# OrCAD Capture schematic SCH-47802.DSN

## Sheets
1 Title, ToC and Rev History: title: X-KIT-TPLSNIFEVB; rev: A; note: SCH-47802 - SPF-47802
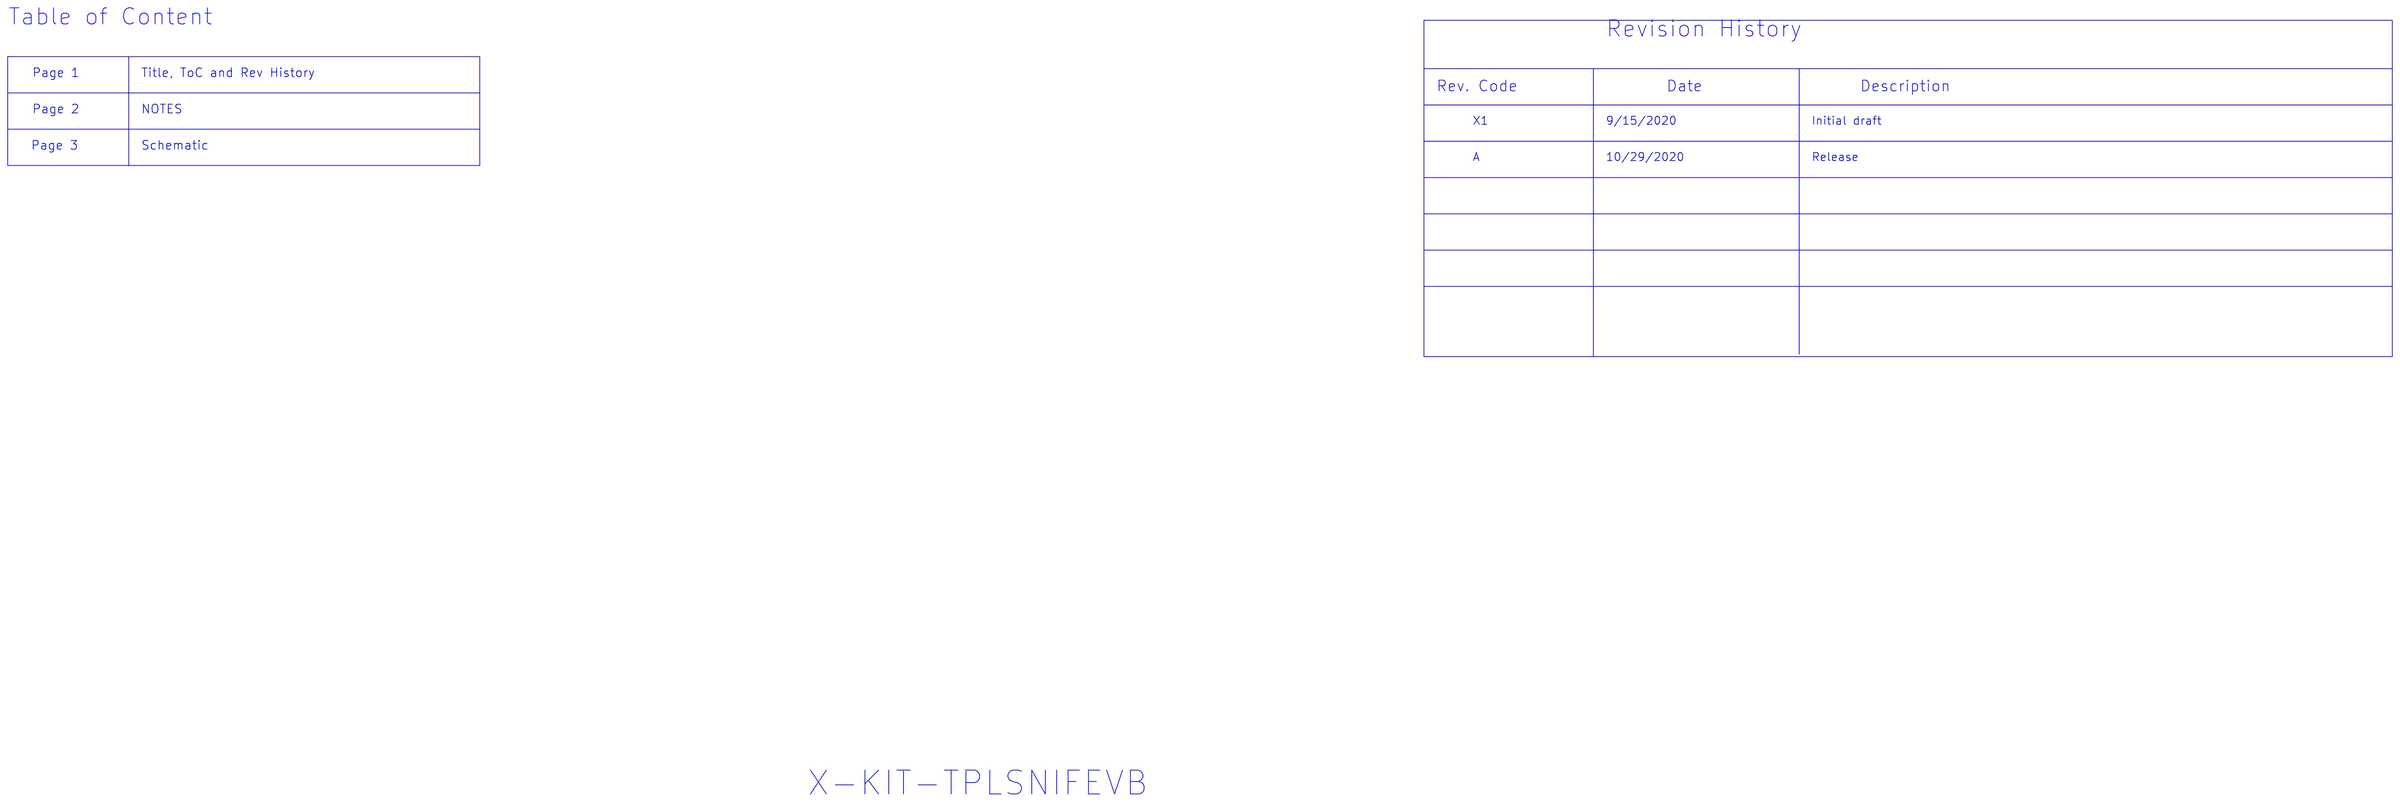
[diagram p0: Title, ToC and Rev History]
2 Notes
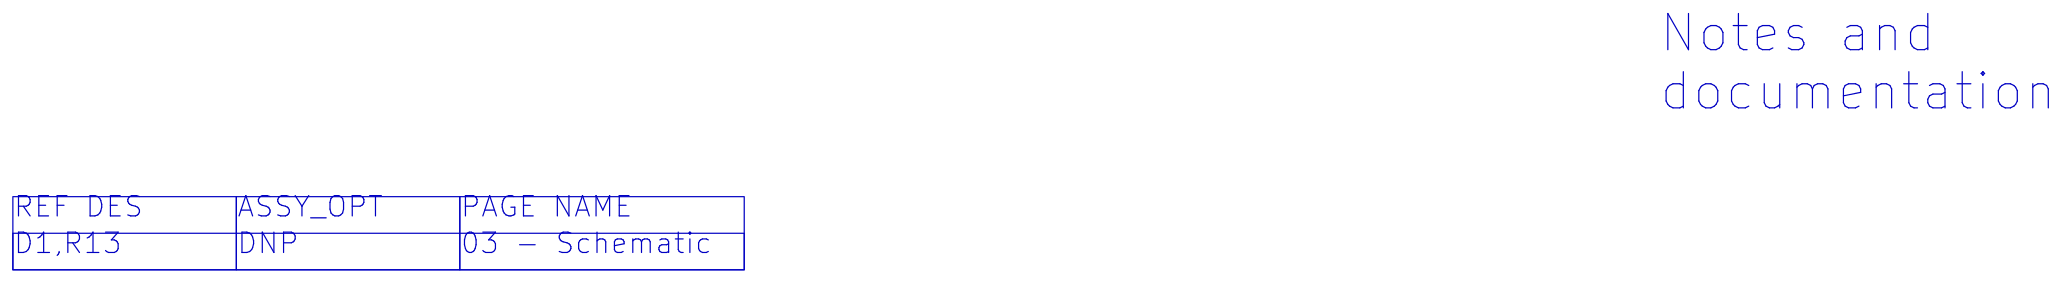
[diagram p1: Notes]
3 Schematic: size C
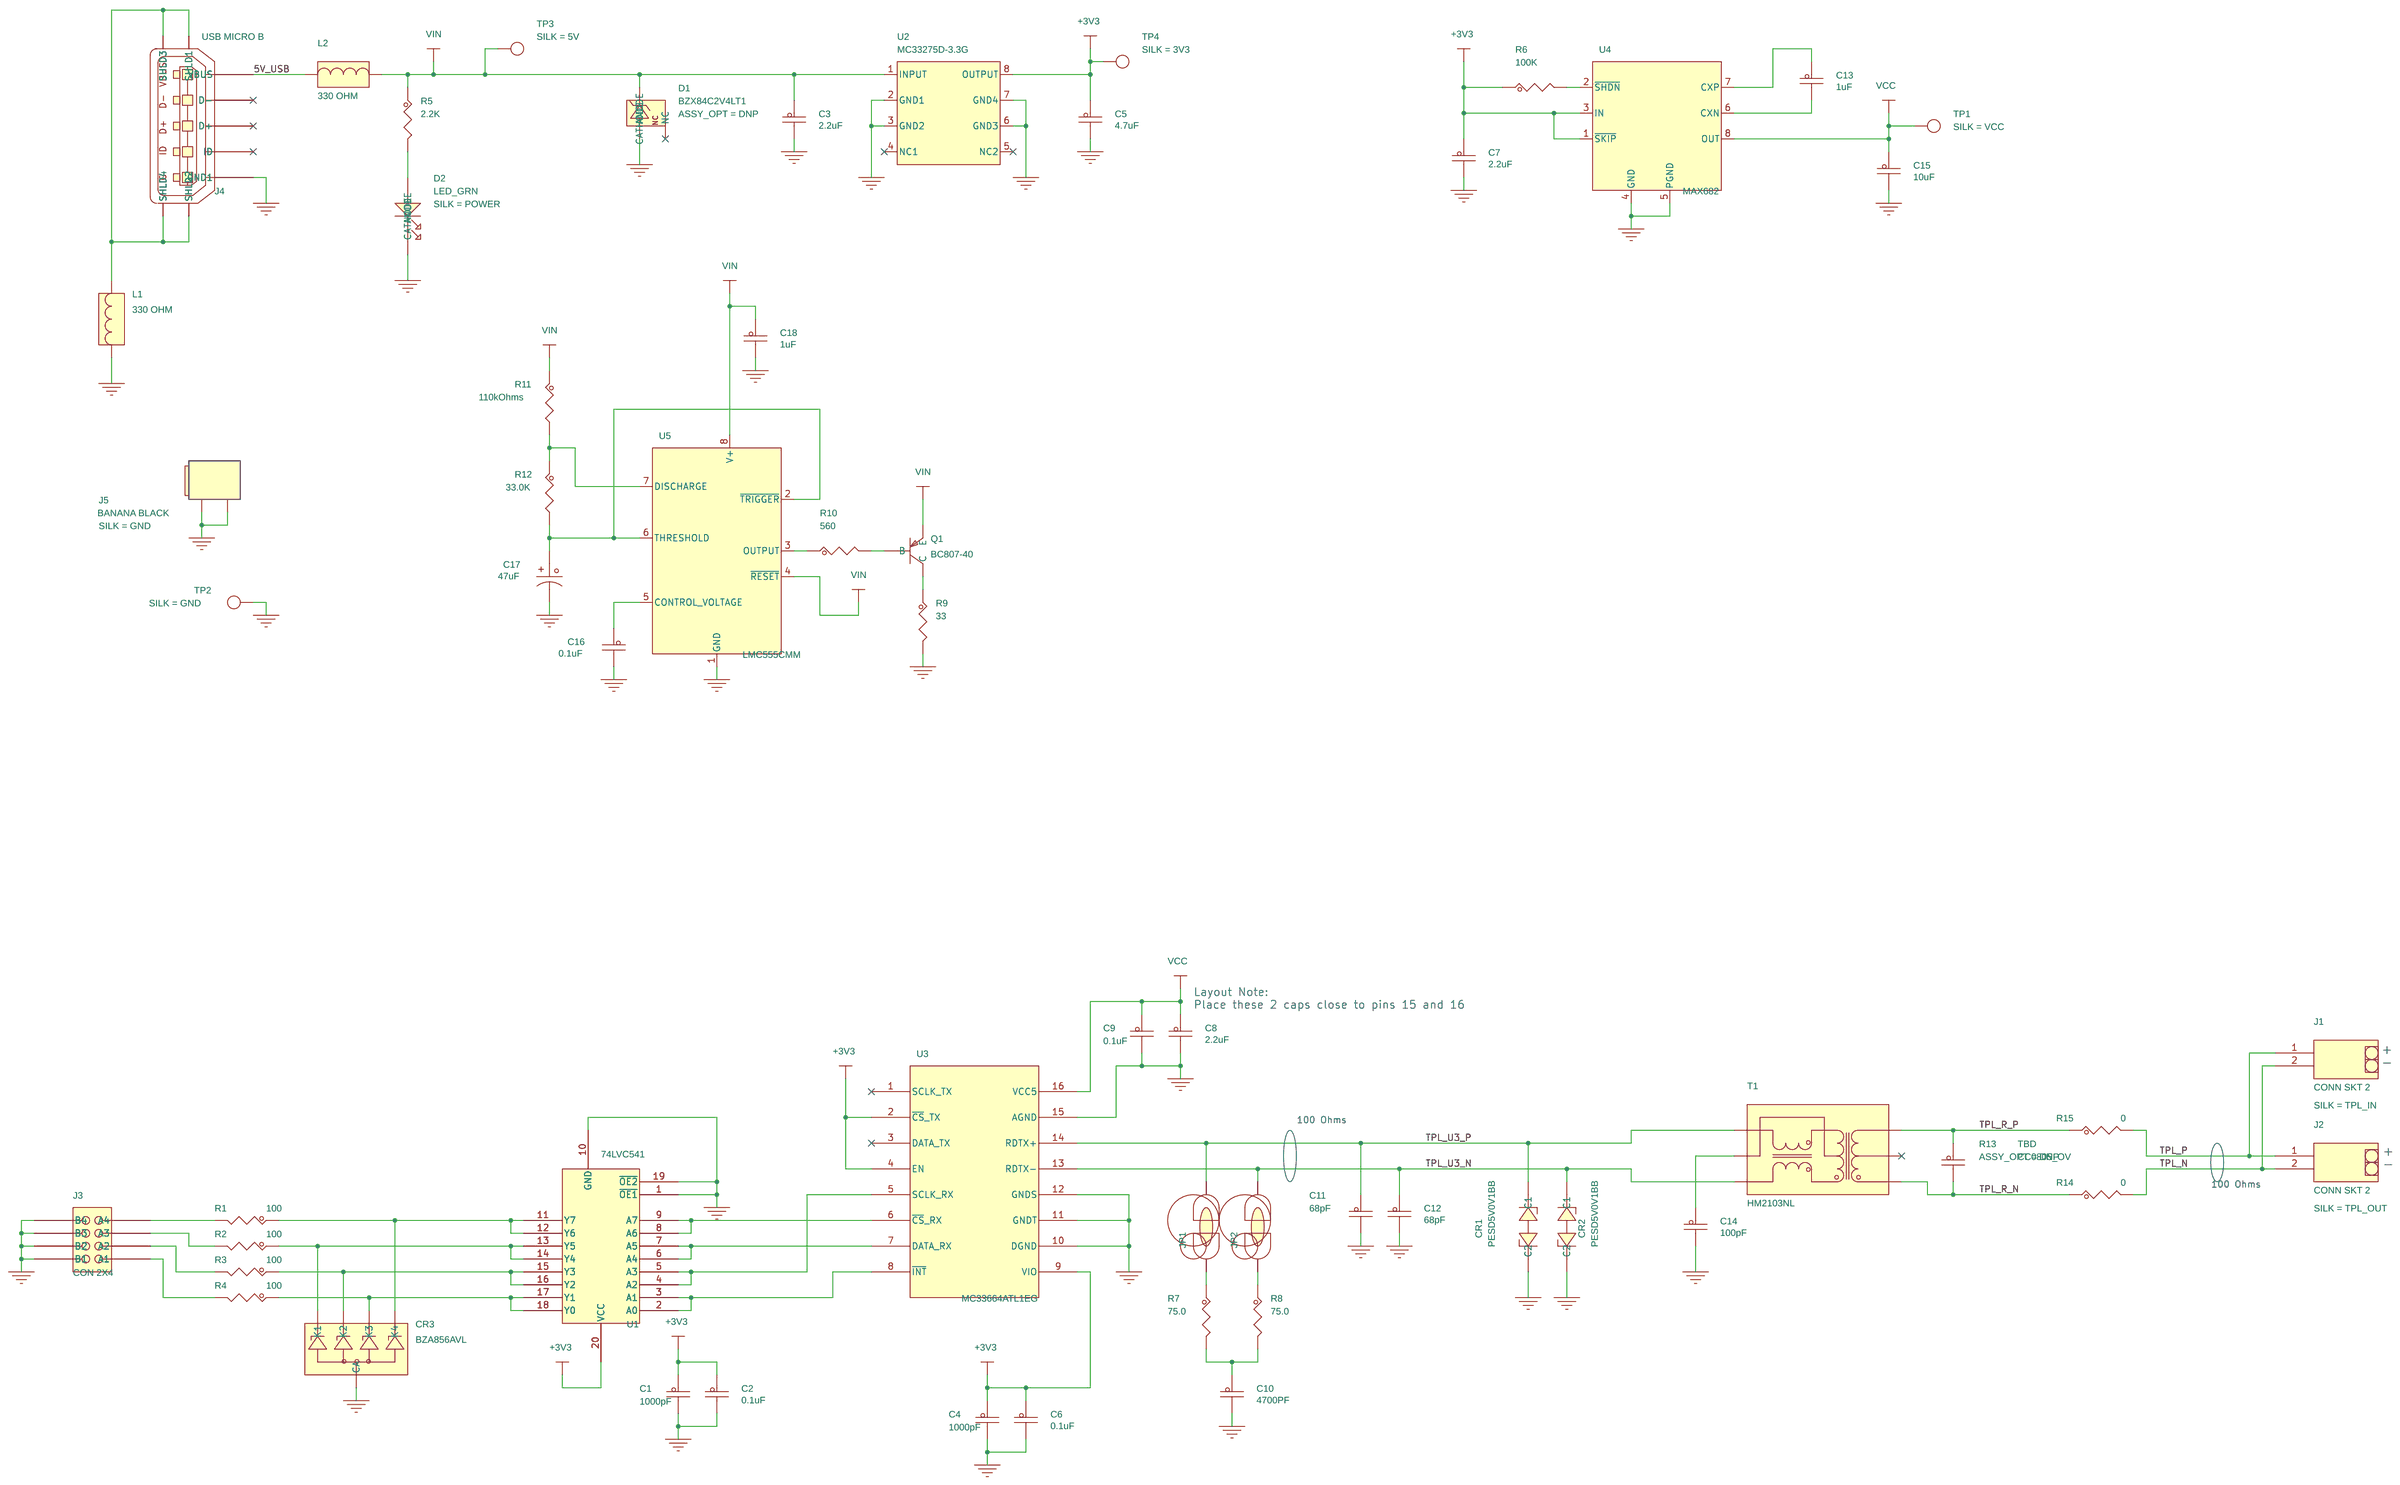
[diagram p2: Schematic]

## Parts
C1  1000pF  [CC0805_OV]
C2  0.1uF  [CC0805_OV]
C3  2.2uF  [CC0805_OV]
C4  1000pF  [CC0805_OV]
C5  4.7uF  [CC0805_OV]
C6  0.1uF  [CC0805_OV]
C7  2.2uF  [CC0805_OV]
C8  2.2uF  [CC0805_OV]
C9  0.1uF  [CC0805_OV]
C10  4700PF  [CC0805_OV]
C11  68pF  [CC0603_OV]
C12  68pF  [CC0603_OV]
C13  1uF  [CC0805_OV]
C14  100pF  [CC0603_OV]
C15  10uF  [CC0805_OV]
C16  0.1uF  [CC0805_OV]
C17  47uF  [CCE5P5X5P5]
C18  1uF  [CC0805_OV]
CR1  PESD5V0V1BB  [sod523_2_diode]
CR2  PESD5V0V1BB  [sod523_2_diode]
CR3  BZA856AVL  [SOT353]
D1  BZX84C2V4LT1  [sot23]
D2  LED_GRN  [led2_2p54_6p6x4p3mm]
J1  CONN SKT 2  [MOLEX-43650-0213]
J2  CONN SKT 2  [MOLEX-43650-0213]
J3  CON 2X4  [con2x4_2p54_ra_th]
J4  USB MICRO B  [usb_micro_b_0p65_sm_ra]
J5  BANANA BLACK  [banana_930224]
JP1  0603_JUMPER  [0603_solder_blob_jumper_open]
JP2  0603_JUMPER  [0603_solder_blob_jumper_open]
L1  330 OHM  [ind_1608]
L2  330 OHM  [ind_1608]
Q1  BC807-40  [SOT-23]
R1  100  [RC0805_OV]
R2  100  [RC0805_OV]
R3  100  [RC0805_OV]
R4  100  [RC0805_OV]
R5  2.2K  [RC0805_OV]
R6  100K  [RC0805_OV]
R7  75.0  [RC0805_OV]
R8  75.0  [RC0805_OV]
R9  33  [RC0805_OV]
R10  560  [RC0805_OV]
R11  110kOhms  [RC0805_OV]
R12  33.0K  [RC0805_OV]
R13  TBD  [CC0805_OV]
R14  0  [RC0805_OV]
R15  0  [RC0805_OV]
T1  HM2103NL  [xfmr6_100_265x300_sm]
TP1  TEST POINT  [tpad_059]
TP2  TEST POINT  [tpad_059]
TP3  TEST POINT  [tpad_059]
TP4  TEST POINT  [tpad_059]
U1  74LVC541  [tssop20]
U2  MC33275D-3.3G  [SO8_1P27_4X5]
U3  MC33664ATL1EG  [SO16_1P27_10X4]
U4  MAX682  [SO8_1P27_4X5]
U5  LMC555CMM  [MSOP_8_0P65_3X3]

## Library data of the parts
C1 C4 = CAP_NP: CAP CER 1000pF 50V 5% C0G AEC-Q200 0805; AGILE_PN: 150-79252; CAD_APPROVED: Yes; FPLIST: CC0805_OV,CC0805,0805_CC; HEIGHT: 0.7MM; MFG_NAME01: YAGEO; MFG_PN01: AC0805JRNPO9BN102; ROHS: Yes; Tolerance: 5%; VOLTAGE: 50V
C2 C6 C9 C16 = CAP_NP: CAP CER 0.1uF 100V 10% X7R AEC-Q200 0805; AGILE_PN: 150-78700; CAD_APPROVED: Yes; FPLIST: CC0805_OV,CC0805,0805_CC; HEIGHT: 1.45MM; MFG_NAME01: MURATA; MFG_PN01: GCM21BR72A104KA37L; Package Size: 0805; Package Type: 180mm Embossed Tape; ROHS: Yes; Tolerance: 10%; VOLTAGE: 100V
C3 C7 C8 = CAP_NP: CAP CER 2.2uF 35V 10% X7R 0805; AGILE_PN: 150-80279; CAD_APPROVED: Yes; FPLIST: CC0805_OV,CC0805,0805_CC; HEIGHT: 1MM; MFG_NAME01: TDK; MFG_PN01: C2012X7R1V225K085AC; Package Size: 0805; ROHS: Yes; Temp Range: -55&#8451; to 125&#8451;; Temp_Range: -55&#8451; to 125&#8451;; Tolerance: 10%; VOLTAGE: 35v
C5 = CAP_NP: CAP CER 4.7uF 25V 10% X7R 0805; AGILE_PN: 150-80282; CAD_APPROVED: Yes; FPLIST: CC0805_OV,CC0805,0805_CC; HEIGHT: 1.45MM; MFG_NAME01: TDK; MFG_PN01: C2012X7R1E475K125AB; Package Size: 0805; ROHS: Yes; Temp Range: -55&#8451; to 125&#8451;; Temp_Range: -55&#8451; to 125&#8451;; Tolerance: 10%; VOLTAGE: 25V
C10 = CAP_NP: CAP CER 4700PF 16V 10% X7R 0805; AGILE_PN: 150-75207; CAD_APPROVED: YES; FPLIST: CC0805_OV,CC0805,0805_CC; HEIGHT: 1.35MM; MFG_NAME01: KEMET; MFG_PN01: C0805C472K4RAC; Package Size: 0805; Package Type: tape & reel; ROHS: Yes; Tolerance: 10%; VOLTAGE: 16V
C11 C12 = CAP_NP: CAP CER 68pF 50V 5% C0G AEC-Q200 0603; AGILE_PN: 150-80056; CAD_APPROVED: Yes; FPLIST: CC0603_OV,CC0603,0603_CC; HEIGHT: 0.9MM; MFG_NAME01: TDK; MFG_PN01: CGA3E2C0G1H680J080AA; ROHS: Yes; Temp Range: -55°C ~ 125°C; Temp_Range: -55°C ~ 125°C; Tolerance: 5%; VOLTAGE: 50V
C13 C18 = CAP_NP: CAP CER 1uF 16V 10% X7R AEC-Q200 0805; AGILE_PN: 150-79006; CAD_APPROVED: Yes; FPLIST: CC0805_OV,CC0805,0805_CC; HEIGHT: 1.45MM; MFG_NAME01: TDK; MFG_PN01: CGA4J2X7R1C105K125AA; Package Size: 0805; ROHS: Yes; Temp Range: -55°C ~ 125°C; Temp_Range: -55°C ~ 125°C; Tolerance: 10%; VOLTAGE: 16V
C14 = CAP_NP: CAP CER 100pF 100V 5% C0G 0603; AGILE_PN: 150-79307; CAD_APPROVED: Yes; FPLIST: CC0603_OV,CC0603,0603_CC; HEIGHT: 0.9 MM; MFG_NAME01: WALSIN TECHNOLOGY CORP.; MFG_PN01: 0603N101J101CT; ROHS: Yes; Tolerance: 5%; VOLTAGE: 100V
C15 = CAP_NP: CAP CER 10UF 10V 10% X7R 0805; AGILE_PN: 150-80285; CAD_APPROVED: Yes; FPLIST: CC0805_OV,CC0805,0805_CC; HEIGHT: 1.40MM; MFG_NAME01: KEMET; MFG_PN01: C0805C106K8RACTU; Package Size: 0805; ROHS: Yes; Temp Range: -50C to 125C; Temp_Range: -50C to 125C
C17 = CAP_POL: CAP ALEL 47uF 16V 20% -- SMT; AGILE_PN: 150-78839; CAD_APPROVED: Yes; HEIGHT: 6.1MM; MFG_NAME01: NIPPON CHEMI-CON CORPORATION; MFG_PN01: EMZJ160ADA470ME61G; Package Type: SMD; ROHS: Yes; Tolerance: 20%; VOLTAGE: 16V
CR1 CR2 = DIODE_BIDIR: DIODE ESD BIDIR 5V AEC-Q101 SOD523; AGILE_PN: 480-80130; CAD_APPROVED: Yes; HEIGHT: 0.65MM; MFG_NAME01: NEXPERIA; MFG_PN01: PESD5V0U1BB; REQUESTED_COMPLETION_DATE: Layout will start in few days; ROHS: Yes; Temp Range: -55°C ~ 150°C; Temp_Range: -55°C ~ 150°C; VOLTAGE: 5V
CR3 = DIODE_ARRAY_4CH_B: DIODE TVS ARRAY UNIDIR ESD 4CH 22pF 5.6V SOT353; AGILE_PN: 480-80168; CAD_APPROVED: Yes; HEIGHT: 1.1MM; MFG_NAME01: NEXPERIA; MFG_PN01: BZA856AVL,115; REQUESTED_COMPLETION_DATE: Original part was marked as Obsolete. I need a replacement quick.; ROHS: Yes; Rated Voltage: 5.6V; VOLTAGE: 5.6V
D1 = DIODEZ_SOT23: DIODE ZNR 225MW 2.4V SOT23; AGILE_PN: 480-76499; ASSY_OPT: DNP; CAD_APPROVED: Yes; HEIGHT: 1.11MM; MFG_NAME01: ON SEMICONDUCTOR; MFG_PN01: BZX84C2V4LT1G; ROHS: Yes; VOLTAGE: 2.4V
D2 = LED: LED GRN SGL RA 25MA TH; AGILE_PN: 370-76483; CAD_APPROVED: Yes; HEIGHT: 7.55MM; MFG_NAME01: KINGBRIGHT; MFG_PN01: L-7104EW/1GD-SH; ROHS: Yes; SILK: POWER
J1 = 43650-0213RTN: CON 2X1 SKT RA SMT 3.0MM 219H AU; 3D_Mechanical_Footprint_File: ftp://fcl.am.freescale.net/ALLEGRO/step/MOLEX-43650-0213.step; AGILE_PN: 211-75284; CAD_APPROVED: Yes; HEIGHT: 5.72 MM; MFG_NAME01: MOLEX; MFG_PN01: 43650-0213; ROHS: Yes; SILK: TPL_IN
J2 = 43650-0213RTN: CON 2X1 SKT RA SMT 3.0MM 219H AU; 3D_Mechanical_Footprint_File: ftp://fcl.am.freescale.net/ALLEGRO/step/MOLEX-43650-0213.step; AGILE_PN: 211-75284; CAD_APPROVED: Yes; HEIGHT: 5.72 MM; MFG_NAME01: MOLEX; MFG_PN01: 43650-0213; ROHS: Yes; SILK: TPL_OUT
J3 = CONN_HDR_4X2: CON 2X4 PLUG RA SHRD TH 100MIL CTR 374H AU 120L; AGILE_PN: 210-82493; CAD_APPROVED: Yes; HEIGHT: 9.5MM; MFG_NAME01: AMPHENOL; MFG_PN01: 75867-132LF; Package Type: Through Hole, Right Angle; ROHS: Yes; Temp Range: -65°C to +125°C
J4 = USB_MINI_B_SKT: CON 5 USB MICRO_B RA SKT SMT 0.65MM SP 117H AU; 3D_Mechanical_Footprint_File: ftp://fcl.am.freescale.net/ALLEGRO/step/usb_micro_b_0p65_sm_ra.STEP; AGILE_PN: 211-80405; CAD_APPROVED: Yes; HEIGHT: 2.96MM; MFG_NAME01: WURTH ELEKTRONIK EISOS GMBH & CO. KG (ELECTRONIC & ELECTROMEHANICAL COMP); MFG_PN01: 629105150521; ROHS: Yes; Temp Range: -40 to +85C
J5 = BANANA_SOCKET: CON 1 BANANA DIN41649 BLACK SKT RA TH -- 228H SN 217L; AGILE_PN: 210-80117; CAD_APPROVED: Yes; HEIGHT: 5.8MM; MFG_NAME01: HIRSCHMANN; MFG_PN01: 930224100; ROHS: Yes; SILK: GND
JP1 JP2 = 2_Pad_Solder_Blob_Jumper_open: SOLDER BLOB JUMPER 0603 OPEN NO PART TO ORDER; AGILE_PN: 470-82290; CAD_APPROVED: Yes; HEIGHT: 0.1MM; MFG_NAME01: NO PART TO ORDER; MFG_PN01: N/A (CUSTOM PCB CONNECTION); ROHS: Yes
L1 L2 = BEAD: IND FER BEAD 330OHM@100MHZ 1.7A 0603; AGILE_PN: 180-78156; CAD_APPROVED: Yes; FPLIST: ind_1608,0603_CC; HEIGHT: 0.95MM; MFG_NAME01: TDK; MFG_PN01: MPZ1608S331A; PART_TYPE: FERRITE\BEAD; ROHS: Yes; Tolerance: 25%
Q1 = PNP: TRAN PNP GEN -45VCE 500MA; AGILE_PN: 480-75918; CAD_APPROVED: Yes; HEIGHT: 1.1MM; MFG_NAME01: PHILIPS SEMICONDUCTOR; ROHS: Yes; Temp Range: -55° C to + 150° C; Temp_Range: -55° C to + 150° C; VOLTAGE: 45V
R1-R4 = RES: RES MF 100 OHM 1/2W 1% AEC-Q200 0805; AGILE_PN: 470-80989; CAD_APPROVED: Yes; FPLIST: RC0805_OV,RC0805,0805_CC; HEIGHT: 0.7 MM; MFG_NAME01: PANASONIC; MFG_PN01: ERJ-P06F1000V; ROHS: Yes; Tolerance: 1%
R5 = RES: RES MF 2.2K 1/8W 1% 0805; AGILE_PN: 470-80739; CAD_APPROVED: Yes; FPLIST: RC0805_OV,RC0805,0805_CC; HEIGHT: 0.7MM; MFG_NAME01: PANASONIC; MFG_PN01: ERJ-6ENF2201V; ROHS: Yes; Tolerance: 1%
R6 = RES: RES MF 100K 1/8W 1% 0805; AGILE_PN: 470-75462; CAD_APPROVED: Yes; FPLIST: RC0805_OV,RC0805,0805_CC; HEIGHT: 0.7 MM; MFG_NAME01: VENKEL COMPANY; MFG_PN01: CR0805-8W-1003FSNT; ROHS: Yes; Tolerance: 1%
R7 R8 = RES: RES TF 75.0 OHM 1/8W 1% 0805; AGILE_PN: 470-76238; CAD_APPROVED: Yes; FPLIST: RC0805_OV,RC0805,0805_CC; HEIGHT: 0.6 MM; MFG_NAME01: YAGEO AMERICA; MFG_PN01: RC0805FR-0775RL; ROHS: Yes; Tolerance: 1%
R9 = RES: RES MF 33 OHM 1/2W 1% AEC-Q200 0805; AGILE_PN: 470-82049; CAD_APPROVED: Yes; FPLIST: RC0805_OV,RC0805,0805_CC; HEIGHT: 0.7MM; MFG_NAME01: PANASONIC; MFG_PN01: ERJP06F33R0V; ROHS: Yes; Temp Range: -55C to +155C; Temp_Range: -55C to +155C; Tolerance: 1%
R10 = RES: RES MF 560 OHM 1/8W 1% 0805; AGILE_PN: 470-77400; CAD_APPROVED: Yes; FPLIST: RC0805_OV,RC0805,0805_CC; HEIGHT: 0.65MM; MFG_NAME01: YAGEO AMERICA; MFG_PN01: RC0805FR-07560RL; ROHS: Yes; Tolerance: 1%; VOLTAGE: 150
R11 = RES: RES MF 110K OHM 1/8W 0.1% AEC-Q200 0805; AGILE_PN: 470-82498; CAD_APPROVED: Yes; FPLIST: RC0805_OV,RC0805,0805_CC; HEIGHT: 0.60mm; MFG_NAME01: PANASONIC; MFG_PN01: ERA-6AEB114V; Package Size: 0805 (2012 Metric); ROHS: Yes; Tolerance: 0.1%
R12 = RES: RES MF 33.0K 1/8W 1% 0805; AGILE_PN: 470-78773; CAD_APPROVED: Yes; FPLIST: RC0805_OV,RC0805,0805_CC; HEIGHT: 0.6 MM; MFG_NAME01: YAGEO AMERICA; MFG_PN01: RC0805FR-0733KL; ROHS: Yes; Tolerance: 1%
R13 = CAP_NP: 0805 Place holder -Layout element only - NO PART TO ORDER; AGILE_PN: 150-79310; ASSY_OPT: DNP; CAD_APPROVED: Yes; FPLIST: CC0805_OV,CC0805,0805_CC; HEIGHT: 0.127 MM; MFG_NAME01: N.A; MFG_PN01: N.A; ROHS: Yes
R14 R15 = RES: RES MF ZERO OHM 1/8W -- 0805; AGILE_PN: 470-75442; CAD_APPROVED: Yes; FPLIST: RC0805_OV,RC0805,RC0805_OV_3P,0805_CC; HEIGHT: 0.7 MM; MFG_NAME01: YAGEO AMERICA; MFG_PN01: RC0805JR-070RL; ROHS: Yes; Temp Range: –55 °C to +155 °C; Temp_Range: –55 °C to +155 °C; Tolerance: 5%
T1 = HM2103NL_6P: XFMR 170-350uH@100KHz 1000VDC AEC-Q200 SMD; AGILE_PN: 560-75718; CAD_APPROVED: Yes; HEIGHT: 5.72MM; MFG_NAME01: PULSE ELECTRONICS; MFG_PN01: HM2103NLT; PART_TYPE: TRANSFORMERS\ISOLATION; ROHS: Yes; Temp Range: -40C to +125C; Temp_Range: -40C to +125C; Tolerance: 2%; VOLTAGE: 1000VDC
TP1 = TestLoop: TEST POINT PAD 59MIL DIA SMT, NO PART TO ORDER; AGILE_PN: 211-77862; CAD_APPROVED: Yes; HEIGHT: 0MM; MFG_NAME01: NOTACOMPONENT; MFG_PN01: NOTACOMPONENT; ROHS: Yes; SILK: VCC
TP2 = TestLoop: TEST POINT PAD 59MIL DIA SMT, NO PART TO ORDER; AGILE_PN: 211-77862; CAD_APPROVED: Yes; HEIGHT: 0MM; MFG_NAME01: NOTACOMPONENT; MFG_PN01: NOTACOMPONENT; ROHS: Yes; SILK: GND
TP3 = TestLoop: TEST POINT PAD 59MIL DIA SMT, NO PART TO ORDER; AGILE_PN: 211-77862; CAD_APPROVED: Yes; HEIGHT: 0MM; MFG_NAME01: NOTACOMPONENT; MFG_PN01: NOTACOMPONENT; ROHS: Yes; SILK: 5V
TP4 = TestLoop: TEST POINT PAD 59MIL DIA SMT, NO PART TO ORDER; AGILE_PN: 211-77862; CAD_APPROVED: Yes; HEIGHT: 0MM; MFG_NAME01: NOTACOMPONENT; MFG_PN01: NOTACOMPONENT; ROHS: Yes; SILK: 3V3
U1 = 74LV541: IC BUF OCTAL DRV TS 1.65-3.6V TSSOP20; AGILE_PN: 312-77607; CAD_APPROVED: Yes; HEIGHT: 1.2MM; MFG_NAME01: TEXAS INSTRUMENTS; MFG_PN01: SN74LVC541APWR; ROHS: Yes; VOLTAGE: 1.65 to 3.6V
U2 = MC33275D_SOIC8: IC VREG LDO 3.3V 0.3A 13V SOIC8; 3D_Mechanical_Footprint_File: ftp://fcl.am.freescale.net/ALLEGRO/step/so8_1p27_4x5.step; AGILE_PN: 312-82307; CAD_APPROVED: Yes; HEIGHT: 1.75MM; MFG_NAME01: ON SEMICONDUCTOR; ROHS: Yes; Temp Range: -40&#8451;~+125&#8451;; Temp_Range: -40&#8451;~+125&#8451;
U3 = MC33664TL_16P: IC XCVR INTERFACE MCU NETWORK 3.3V/5V SO16; AGILE_PN: 312-81005; CAD_APPROVED: Yes; HEIGHT: 1.75MM; MFG_NAME01: FREESCALE SEMICONDUCTOR; ROHS: Yes; VOLTAGE: 3.3V/5V
U4 = MAX682: IC VREG DCDC CHARGE PUMP SWT 5V 0.3A 2.7-5.5V SO8; 3D_Mechanical_Footprint_File: ftp://fcl.am.freescale.net/ALLEGRO/step/so8_1p27_4x5.step; AGILE_PN: 315-82158; CAD_APPROVED: Yes; HEIGHT: 1.75MM; MFG_NAME01: MAXIM; MFG_PN01: MAX682ESA+; ROHS: Yes; Temp Range: -40°C to 85°C; Temp_Range: -40°C to 85°C
U5 = LMC555CMM_8P: IC TIMER 15V VSSOP8; AGILE_PN: 315-81544; CAD_APPROVED: Yes; HEIGHT: 1.1MM; MFG_NAME01: TEXAS INSTRUMENTS; MFG_PN01: LMC555CMM/NOPB; ROHS: Yes; Temp Range: -40C to +85C; Temp_Range: -40C to +85C; VOLTAGE: 15V

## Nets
5V_USB: J4.1(VBUS) L2.1
+3V3: C1.1 C2.1 C4.1 C5.1 C6.1 C7.1 R6.1 TP4.1(Pin1) U1.20(VCC) U2.8(OUTPUT) U3.2(~{CS}_TX) U3.4(EN) U3.9(VIO) U4.1(~{SKIP}) U4.3(IN)
GND: C1.2 C2.2 C3.2 C4.2 C5.2 C6.2 C7.2 C8.2 C9.2 C10.2 C11.2 C12.2 C14.2 C15.2 C16.2 C17.2 C18.2 CR1.2(C2) CR2.2(C2) CR3.2(CA) D1.1(ANODE) D2.C(CATHODE) J3.2(B1) J3.4(B2) J3.6(B3) J3.8(B4) J4.5(GND1) J5.1 J5.2 L1.2 R9.2 TP2.1(Pin1) U1.1(~{OE1}) U1.10(GND) U1.19(~{OE2}) U2.2(GND1) U2.3(GND2) U2.6(GND3) U2.7(GND4) U3.10(DGND) U3.11(GNDT) U3.12(GNDS) U3.15(AGND) U4.4(GND) U4.5(PGND) U5.1(GND)
VCC: C8.1 C9.1 C15.1 TP1.1(Pin1) U3.16(VCC5) U4.8(OUT)
Vin: C3.1 C18.1 D1.3(CATHODE) L2.2 Q1.2(E) R5.1 R11.1 TP3.1(Pin1) U2.1(INPUT) U5.4(~{RESET}) U5.8(V+)
TPL_N: J1.2 J2.2 R14.2
TPL_P: J1.1 J2.1 R15.2
TPL_R_N: R13.2 R14.1 T1.1
TPL_R_P: R13.1 R15.1 T1.3
TPL_U3_N: C12.1 CR2.1(C1) JP2.1 T1.6 U3.13(RDTX-)
TPL_U3_P: C11.1 CR1.1(C1) JP1.1 T1.4 U3.14(RDTX+)
N18140284: J4.S1(SHLD1) J4.S2(SHLD2) J4.S3(SHLD3) J4.S4(SHLD4) L1.1
N18140514: D2.A(ANODE) R5.2
N18140821: C17.1 R12.2 U5.2(~{TRIGGER}) U5.6(THRESHOLD)
N18141244: Q1.3(C) R9.1
N18141629: R11.2 R12.1 U5.7(DISCHARGE)
N18141865: C16.1 U5.5(CONTROL_VOLTAGE)
N18141901: R6.2 U4.2(~{SHDN})
N18142113: C13.2 U4.6(CXN)
N18142118: C13.1 U4.7(CXP)
N18142920: U1.8(A6) U1.9(A7) U3.6(~{CS}_RX)
N18142968: U1.6(A4) U1.7(A5) U3.7(DATA_RX)
N18142993: U1.4(A2) U1.5(A3) U3.5(SCLK_RX)
N18143018: U1.2(A0) U1.3(A1) U3.8(~{INT})
N18146386: JP1.2 R7.1
N18146399: JP2.2 R8.1
N18146402: C10.1 R7.2 R8.2
N18148289: C14.1 T1.5
N18148755: R10.1 U5.3(OUTPUT)
N18148758: Q1.1(B) R10.2
N18157351: J3.7(A4) R1.2
N18157353: CR3.5(K4) R1.1 U1.11(Y7) U1.12(Y6)
N18157371: J3.5(A3) R2.2
N18157393: J3.3(A2) R3.2
N18157399: CR3.1(K1) R2.1 U1.13(Y5) U1.14(Y4)
N18157417: J3.1(A1) R4.2
N18157439: CR3.3(K2) R3.1 U1.15(Y3) U1.16(Y2)
N18157469: CR3.4(K3) R4.1 U1.17(Y1) U1.18(Y0)

Not connected (* = marked no-connect by the designer): D1 2(NC)*; J4 2(D-)* 3(D+)* 4(ID)*; T1 2*; U2 4(NC1)* 5(NC2)*; U3 1(SCLK_TX)* 3(DATA_TX)*

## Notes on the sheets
sheet 1
- Table of Content
- Revision History
- Page 1
- Title, ToC and Rev History
- Rev. Code
- Date
- Description
- Page 2
- NOTES
- X1
- 9/15/2020
- Initial draft
- Page 3
- Schematic
- A
- 10/29/2020
- Release
- X-KIT-TPLSNIFEVB
sheet 2
- Notes and
  documentation
- REF DES
- ASSY_OPT
- PAGE NAME
- D1,R13
- DNP
- 03 - Schematic
sheet 3
- Layout Note:
  Place these 2 caps close to pins 15 and 16
- +
- -
- 100 Ohms
- +
- -
- 100 Ohms
